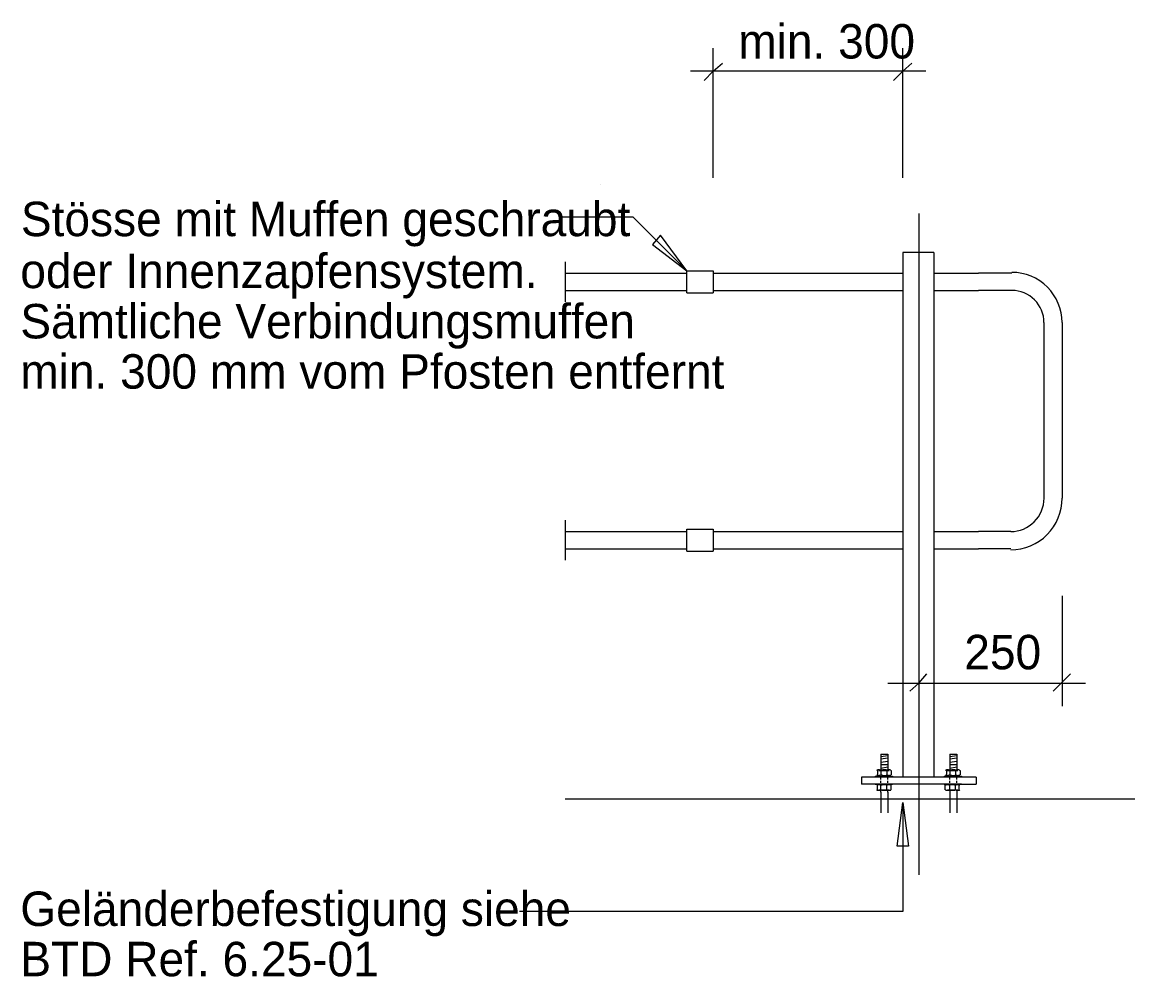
# Model space of a CAD drawing. Extents: x 0.726 to 0.882, y -0.271 to -0.058.
# Drawn here: x 0.7387 to 0.8356, y -0.2714 to -0.1882 of the extents above; entities that cross this region are included whole.
import ezdxf

# ---------------------------------------------------------------- set-up
doc = ezdxf.new("R2010")
doc.units = 0
doc.layers.add('Ebene_02', color=7, linetype='Continuous')

msp = doc.modelspace()

# ---------------------------------------------------------------- linework, layer by layer
at = {"layer": 'Ebene_02'}
for p, q in [((0.7989, -0.2018), (0.7989, -0.1905)), ((0.8154, -0.2018), (0.8154, -0.1905)), ((0.7989, -0.1925), (0.7997000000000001, -0.1918)), ((0.8154, -0.1925), (0.8162, -0.1918)), ((0.8174, -0.1925), (0.7969, -0.1925)), ((0.7989, -0.1925), (0.7981, -0.1933)), ((0.7989, -0.1925), (0.7989, -0.1925)), ((0.8154, -0.1925), (0.8146, -0.1933)), ((0.8154, -0.19210000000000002), (0.8154, -0.19210000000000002)), ((0.7891, -0.2024), (0.7891, -0.2024)), ((0.7855133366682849, -0.20520000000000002), (0.7919, -0.20520000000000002)), ((0.7966000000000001, -0.2099), (0.7919, -0.20520000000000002)), ((0.8168000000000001, -0.2049), (0.8168000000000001, -0.2625)), ((0.7943, -0.2068), (0.7936000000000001, -0.2076)), ((0.7966000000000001, -0.2099), (0.7943, -0.2068)), ((0.7936000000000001, -0.2076), (0.7966000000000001, -0.2099)), ((0.786, -0.2091), (0.786, -0.2126)), ((0.8181, -0.2083), (0.8154, -0.2083)), ((0.8154, -0.2083), (0.8154, -0.254)), ((0.8181, -0.2083), (0.8181, -0.254)), ((0.786, -0.2101), (0.7966000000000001, -0.2101)), ((0.7966000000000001, -0.21180000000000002), (0.7966000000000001, -0.2099)), ((0.7966000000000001, -0.2099), (0.7989, -0.2099)), ((0.7966000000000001, -0.2099), (0.7966000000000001, -0.2099)), ((0.7989, -0.2099), (0.7989, -0.21180000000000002)), ((0.7989, -0.2101), (0.8154, -0.2101)), ((0.8181, -0.2101), (0.8220000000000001, -0.2101)), ((0.8249000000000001, -0.2101), (0.8220000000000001, -0.2101)), ((0.786, -0.2116), (0.7966000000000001, -0.2116)), ((0.7966000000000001, -0.21180000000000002), (0.7989, -0.21180000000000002)), ((0.7989, -0.2116), (0.8154, -0.2116)), ((0.8181, -0.2116), (0.8220000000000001, -0.2116)), ((0.8249000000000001, -0.2116), (0.8220000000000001, -0.2116)), ((0.8277, -0.22970000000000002), (0.8277, -0.2144)), ((0.8293, -0.22970000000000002), (0.8293, -0.2144)), ((0.786, -0.2316), (0.786, -0.2351)), ((0.7966000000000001, -0.2343), (0.7966000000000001, -0.23240000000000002)), ((0.7966000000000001, -0.23240000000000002), (0.7989, -0.23240000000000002)), ((0.7989, -0.23240000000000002), (0.7989, -0.2343)), ((0.786, -0.2326), (0.7966000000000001, -0.2326)), ((0.7989, -0.2326), (0.8154, -0.2326)), ((0.8181, -0.2326), (0.8220000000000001, -0.2326)), ((0.8248000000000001, -0.2326), (0.8220000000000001, -0.2326)), ((0.786, -0.2341), (0.7966000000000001, -0.2341)), ((0.7966000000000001, -0.2343), (0.7989, -0.2343)), ((0.7989, -0.2341), (0.8154, -0.2341)), ((0.8181, -0.2341), (0.8220000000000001, -0.2341)), ((0.8248000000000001, -0.2341), (0.8220000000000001, -0.2341)), ((0.8293, -0.24780000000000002), (0.8293, -0.23820000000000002)), ((0.8168000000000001, -0.24580000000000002), (0.8175, -0.24500000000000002)), ((0.8293, -0.2457), (0.8300000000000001, -0.24500000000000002)), ((0.8141, -0.24580000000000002), (0.8313, -0.24580000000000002)), ((0.8168000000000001, -0.24580000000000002), (0.8160000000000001, -0.24650000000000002)), ((0.8293, -0.2457), (0.8285, -0.24650000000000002)), ((0.8135, -0.252), (0.8141, -0.252)), ((0.8135, -0.252), (0.8135, -0.2534)), ((0.8135, -0.25220000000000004), (0.8141, -0.2521)), ((0.8135, -0.2524), (0.8141, -0.2523)), ((0.8135, -0.25270000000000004), (0.8141, -0.2526)), ((0.8141, -0.252), (0.8141, -0.2534)), ((0.8195, -0.252), (0.8201, -0.252)), ((0.8195, -0.252), (0.8195, -0.2534)), ((0.8195, -0.25220000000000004), (0.8201, -0.2521)), ((0.8195, -0.2524), (0.8201, -0.2523)), ((0.8195, -0.25270000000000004), (0.8201, -0.2526)), ((0.8201, -0.252), (0.8201, -0.2534)), ((0.8132, -0.2534), (0.8132, -0.2538)), ((0.8133, -0.2534), (0.8142, -0.2534)), ((0.8135, -0.2529), (0.8141, -0.2529)), ((0.8135, -0.25320000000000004), (0.8141, -0.2531)), ((0.8135, -0.2534), (0.8135, -0.2538)), ((0.8139000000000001, -0.2534), (0.8140000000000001, -0.2534)), ((0.8140000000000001, -0.2534), (0.8140000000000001, -0.2538)), ((0.8144, -0.2534), (0.8144, -0.2538)), ((0.8192, -0.2534), (0.8192, -0.2538)), ((0.8193, -0.2534), (0.8202, -0.2534)), ((0.8195, -0.2529), (0.8201, -0.2529)), ((0.8195, -0.25320000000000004), (0.8201, -0.2531)), ((0.8195, -0.2534), (0.8195, -0.2538)), ((0.8201, -0.2534), (0.8199000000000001, -0.2534)), ((0.8200000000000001, -0.2534), (0.8200000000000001, -0.2538)), ((0.8204, -0.2534), (0.8204, -0.2538)), ((0.8118000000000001, -0.254), (0.8118000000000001, -0.2546)), ((0.8218000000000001, -0.254), (0.8118000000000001, -0.254)), ((0.8205, -0.2546), (0.8118000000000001, -0.2546)), ((0.8130000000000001, -0.2539), (0.8130000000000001, -0.254)), ((0.8130000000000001, -0.2539), (0.8145, -0.2539)), ((0.8130000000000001, -0.2546), (0.8130000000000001, -0.2546)), ((0.8130000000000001, -0.2546), (0.8145, -0.2546)), ((0.8132, -0.2551), (0.8132, -0.25470000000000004)), ((0.8135, -0.25420000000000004), (0.8135, -0.254)), ((0.8135, -0.2545), (0.8135, -0.2543)), ((0.8135, -0.2551), (0.8135, -0.25470000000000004)), ((0.8140000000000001, -0.2551), (0.8140000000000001, -0.25470000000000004)), ((0.8141, -0.25420000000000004), (0.8141, -0.254)), ((0.8141, -0.2545), (0.8141, -0.2543)), ((0.8144, -0.2551), (0.8144, -0.25470000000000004)), ((0.8145, -0.2539), (0.8145, -0.254)), ((0.8145, -0.2546), (0.8145, -0.2546)), ((0.8190000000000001, -0.2539), (0.8190000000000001, -0.254)), ((0.8190000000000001, -0.2539), (0.8205, -0.2539)), ((0.8190000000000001, -0.2546), (0.8190000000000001, -0.2546)), ((0.8190000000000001, -0.2546), (0.8205, -0.2546)), ((0.8191, -0.2551), (0.8191, -0.25470000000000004)), ((0.8195, -0.25420000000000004), (0.8195, -0.254)), ((0.8195, -0.2545), (0.8195, -0.2543)), ((0.8195, -0.2551), (0.8195, -0.25470000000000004)), ((0.8200000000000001, -0.2551), (0.8200000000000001, -0.25470000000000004)), ((0.8201, -0.25420000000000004), (0.8201, -0.254)), ((0.8201, -0.2545), (0.8201, -0.2543)), ((0.8203, -0.2551), (0.8203, -0.25470000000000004)), ((0.8205, -0.2539), (0.8205, -0.254)), ((0.8205, -0.2546), (0.8205, -0.2546)), ((0.8205, -0.2546), (0.8218000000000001, -0.2546)), ((0.8218000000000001, -0.254), (0.8218000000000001, -0.2546)), ((0.8133, -0.2551), (0.8142, -0.2551)), ((0.8135, -0.2553), (0.8135, -0.2551)), ((0.8135, -0.2553), (0.8135, -0.2571)), ((0.8141, -0.2553), (0.8141, -0.2551)), ((0.8141, -0.2553), (0.8141, -0.2571)), ((0.8193, -0.2551), (0.8202, -0.2551)), ((0.8195, -0.2551), (0.8195, -0.2553)), ((0.8195, -0.2553), (0.8195, -0.2571)), ((0.8201, -0.2551), (0.8201, -0.2553)), ((0.8201, -0.2553), (0.8201, -0.2571)), ((0.7928000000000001, -0.2559), (0.786, -0.2559)), ((0.8168000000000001, -0.2559), (0.7928000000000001, -0.2559)), ((0.8149000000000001, -0.26), (0.8154, -0.25620000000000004)), ((0.8154, -0.25620000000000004), (0.8159000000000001, -0.26)), ((0.8154, -0.25620000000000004), (0.8154, -0.2657)), ((0.8356, -0.2559), (0.8168000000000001, -0.2559)), ((0.8159000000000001, -0.26), (0.8149000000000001, -0.26)), ((0.8154, -0.2657), (0.7820079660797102, -0.2657))]:
    msp.add_line(p, q, dxfattribs=at)
for points in [[(0.7966000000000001, -0.20980000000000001), (0.7966000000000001, -0.20980000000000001)], [(0.8277, -0.22970000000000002), (0.8277, -0.22970000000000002)], [(0.8293, -0.22970000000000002), (0.8293, -0.22970000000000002)], [(0.8293, -0.2457), (0.8293, -0.2457)]]:
    msp.add_lwpolyline(points, close=True, dxfattribs=at)
for centre, radius, start, end in [((0.8249000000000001, -0.2144), 0.004373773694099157, 0, 90.01698055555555), ((0.8249000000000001, -0.2144), 0.002793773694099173, 0, 90.01698055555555), ((0.8248000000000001, -0.22970000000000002), 0.0029015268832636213, 270.05094444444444, 0.06792500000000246), ((0.8248000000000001, -0.22970000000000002), 0.00448152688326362, 270.05094444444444, 0.06792500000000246)]:
    msp.add_arc(centre, radius, start, end, dxfattribs=at)
for centre, major_axis, ratio, start_param, end_param in [((0.8133, -0.2534), (-0.00016621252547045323, 2.0355163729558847e-20), 0.22718841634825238, 3.084898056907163, 6.341657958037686), ((0.8133, -0.2538), (-0.00016621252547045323, 2.0355163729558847e-20), 0.22718841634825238, 6.227083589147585, 9.483843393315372), ((0.8138000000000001, -0.2534), (-0.00026864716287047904, 3.2899788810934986e-20), 0.14136656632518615, 3.0795212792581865, 6.347034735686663), ((0.8138000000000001, -0.2538), (-0.00026864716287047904, 3.2899788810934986e-20), 0.14136656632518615, 6.221706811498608, 9.48922017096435), ((0.8142, -0.2534), (0.00016621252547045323, 0), 0.22718841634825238, 6.227083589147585, 9.483843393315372), ((0.8142, -0.2538), (0.00016621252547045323, 0), 0.22718841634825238, 3.084898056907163, 6.341657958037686), ((0.8193, -0.2534), (-0.00016621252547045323, 2.0355163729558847e-20), 0.22718841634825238, 3.084898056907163, 6.341657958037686), ((0.8193, -0.2538), (-0.00016621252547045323, 2.0355163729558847e-20), 0.22718841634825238, 6.227083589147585, 9.483843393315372), ((0.8198000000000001, -0.2534), (-0.00026864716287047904, 3.2899788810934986e-20), 0.14136656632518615, 3.0795212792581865, 6.347034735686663), ((0.8198000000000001, -0.2538), (-0.00026864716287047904, 3.2899788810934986e-20), 0.14136656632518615, 6.221706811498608, 9.48922017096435), ((0.8202, -0.2534), (0.00016621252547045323, 0), 0.22718841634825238, 6.227083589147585, 9.483843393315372), ((0.8202, -0.2538), (0.00016621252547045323, 0), 0.22718841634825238, 3.084898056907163, 6.341657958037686), ((0.8133, -0.25470000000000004), (-0.00016621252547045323, 2.0355163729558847e-20), 0.22718841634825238, 3.084898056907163, 6.341657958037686), ((0.8138000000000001, -0.25470000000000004), (-0.00026864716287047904, 3.2899788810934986e-20), 0.14136656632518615, 3.0795212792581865, 6.347034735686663), ((0.8142, -0.25470000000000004), (0.00016621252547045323, 0), 0.22718841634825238, 6.227083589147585, 9.483843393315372), ((0.8193, -0.25470000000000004), (-0.00016621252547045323, 2.0355163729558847e-20), 0.22718841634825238, 3.084898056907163, 6.341657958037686), ((0.8197, -0.25470000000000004), (-0.00026864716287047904, 3.2899788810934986e-20), 0.14136656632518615, 3.0795212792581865, 6.347034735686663), ((0.8202, -0.25470000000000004), (0.00016621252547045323, 0), 0.22718841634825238, 6.227083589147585, 9.483843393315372), ((0.8133, -0.2551), (-0.00016621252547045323, 2.0355163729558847e-20), 0.22718841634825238, 6.227083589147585, 9.483843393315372), ((0.8138000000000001, -0.2551), (-0.00026864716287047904, 3.2899788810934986e-20), 0.14136656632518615, 6.221706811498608, 9.48922017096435), ((0.8142, -0.2551), (0.00016621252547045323, 0), 0.22718841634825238, 3.084898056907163, 6.341657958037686), ((0.8193, -0.2551), (-0.00016621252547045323, 2.0355163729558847e-20), 0.22718841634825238, 6.227083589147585, 9.483843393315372), ((0.8197, -0.2551), (-0.00026864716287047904, 3.2899788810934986e-20), 0.14136656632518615, 6.221706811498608, 9.48922017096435), ((0.8202, -0.2551), (0.00016621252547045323, 0), 0.22718841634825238, 3.084898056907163, 6.341657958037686)]:
    msp.add_ellipse(centre, major_axis=major_axis, ratio=ratio, start_param=start_param, end_param=end_param, dxfattribs=at)

# ---------------------------------------------------------------- texts
for s, p in [('min. 300', (0.8010782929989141, -0.19140000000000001)), ('Stösse mit Muffen geschraubt', (0.7386032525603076, -0.2068732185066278)), ('oder Innenzapfensystem.', (0.7385522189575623, -0.21140009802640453)), ('Sämtliche Verbindungsmuffen', (0.7385522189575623, -0.21577806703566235)), ('min. 300 mm vom Pfosten entfernt', (0.7385522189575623, -0.22015603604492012)), ('250', (0.8207564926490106, -0.2446)), ('Geländerbefestigung siehe', (0.7385522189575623, -0.2669586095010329)), ('BTD Ref. 6.25-01', (0.7385522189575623, -0.2713365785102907))]:
    msp.add_text(s, height=0.003, dxfattribs=at).set_placement(p)

doc.saveas('drawing.dxf')
